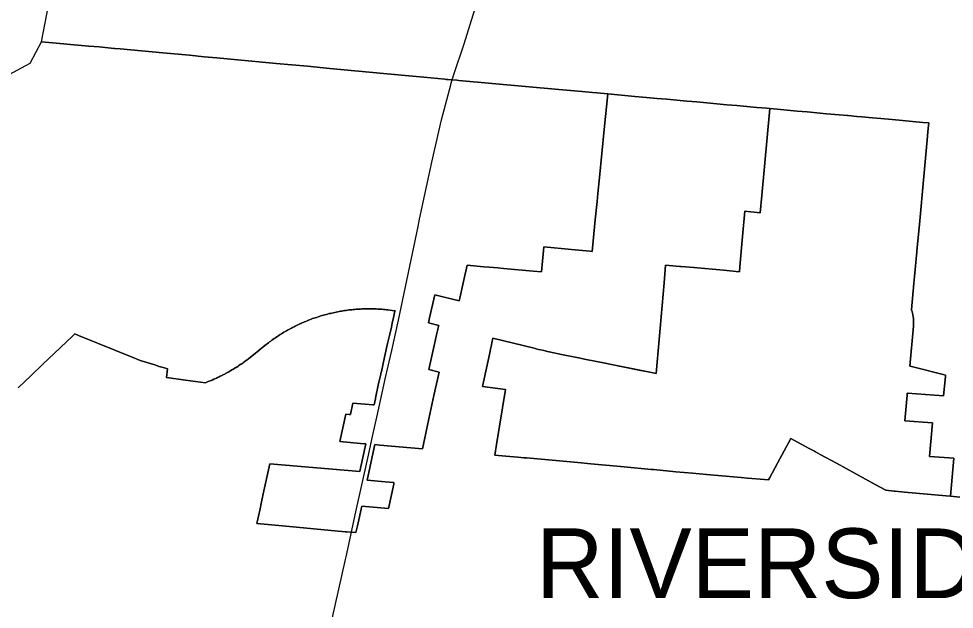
# Model space of a CAD drawing. Extents: x 0 to 34, y 0 to 22.
# Drawn here: x 5.4737 to 5.5815, y 15.4958 to 15.5639 of the extents above; entities that cross this region are included whole.
import ezdxf

# ---------------------------------------------------------------- set-up
doc = ezdxf.new("R2010")
doc.units = 0
for name, color, linetype in [('GM_X_Corporation', 7, 'Continuous'), ('GM_X_Corporation_Text', 7, 'Continuous'), ('GM_X_State_Route', 7, 'Continuous')]:
    doc.layers.add(name, color=color, linetype=linetype)

msp = doc.modelspace()

# ---------------------------------------------------------------- linework, layer by layer
at = {"layer": 'GM_X_Corporation'}
for points in [[(5.58209, 15.50876), (5.58101, 15.50886), (5.58141, 15.51326), (5.5786, 15.51346), (5.57896, 15.51734), (5.57575, 15.51757), (5.57602, 15.5205), (5.57604, 15.52074), (5.57606, 15.52074), (5.58021, 15.52043), (5.58043, 15.52265), (5.58044, 15.52283), (5.58019, 15.5229), (5.57655, 15.52381), (5.57633, 15.52387), (5.57676, 15.52848), (5.57676, 15.52856), (5.57677, 15.52864), (5.57677, 15.52871), (5.57677, 15.52879), (5.57678, 15.52887), (5.57678, 15.52894), (5.57677, 15.52902), (5.57677, 15.5291), (5.57677, 15.52917), (5.57676, 15.52925), (5.57675, 15.52933), (5.57675, 15.52941), (5.57674, 15.52946), (5.57674, 15.52948), (5.57673, 15.52956), (5.57671, 15.52963), (5.5767, 15.52971), (5.57669, 15.52979), (5.57667, 15.52986), (5.57665, 15.52994), (5.57663, 15.53001), (5.57661, 15.53008), (5.57659, 15.53016), (5.57657, 15.53023), (5.57653, 15.53035), (5.57653, 15.53035), (5.57673, 15.53253), (5.57677, 15.53293), (5.57681, 15.53341), (5.57688, 15.53418), (5.57715, 15.53705), (5.57715, 15.53709), (5.57748, 15.5406), (5.57791, 15.54529), (5.5783, 15.54951), (5.57846, 15.55126), (5.57852, 15.55189), (5.57782, 15.55195), (5.57665, 15.55205), (5.57548, 15.55216), (5.57432, 15.55227), (5.57298, 15.55239), (5.57202, 15.55247), (5.57082, 15.55258), (5.57023, 15.55263), (5.56922, 15.55273), (5.56914, 15.55273), (5.56819, 15.55282), (5.56673, 15.55295), (5.56561, 15.55305), (5.5645, 15.55315), (5.56335, 15.55326), (5.56219, 15.55336), (5.56104, 15.55347), (5.56022, 15.55354), (5.55988, 15.55357), (5.55873, 15.55367), (5.55758, 15.55378), (5.55642, 15.55388), (5.55527, 15.55399), (5.55411, 15.55409), (5.55296, 15.5542), (5.55181, 15.5543), (5.55065, 15.5544), (5.5495, 15.55451), (5.54834, 15.55461), (5.54719, 15.55472), (5.54602, 15.55482), (5.54467, 15.55494), (5.54351, 15.55505), (5.54271, 15.55512), (5.54154, 15.55523), (5.54028, 15.55534), (5.53978, 15.55539), (5.53858, 15.5555), (5.53589, 15.55574), (5.52438, 15.55678), (5.52417, 15.5568), (5.52364, 15.55685), (5.52361, 15.55685), (5.5231, 15.5569), (5.52291, 15.55691), (5.52278, 15.55693), (5.52036, 15.55715), (5.51863, 15.55731), (5.51405, 15.55774), (5.50953, 15.55817), (5.50694, 15.55841), (5.50334, 15.55875), (5.50136, 15.55893), (5.50054, 15.55901), (5.50054, 15.55901), (5.49888, 15.55916), (5.49651, 15.55938), (5.49505, 15.55952), (5.49337, 15.55968), (5.49029, 15.55996), (5.48661, 15.5603), (5.48538, 15.56041), (5.48474, 15.56047), (5.48468, 15.56048), (5.48295, 15.56064), (5.48174, 15.56075), (5.4763, 15.56125), (5.47806, 15.57044)], [(5.47209, 15.55721), (5.47501, 15.55879), (5.4763, 15.56125), (5.48174, 15.56075), (5.48295, 15.56064), (5.48468, 15.56048), (5.48474, 15.56047), (5.48538, 15.56042), (5.48661, 15.5603), (5.49029, 15.55996), (5.49337, 15.55968), (5.49505, 15.55952), (5.49651, 15.55938), (5.49888, 15.55916), (5.50053, 15.55901), (5.50136, 15.55893), (5.50334, 15.55875), (5.50694, 15.55841), (5.50953, 15.55817), (5.51405, 15.55774), (5.51863, 15.55731), (5.52035, 15.55715), (5.52278, 15.55693), (5.52291, 15.55691), (5.5231, 15.5569), (5.52361, 15.55685), (5.52364, 15.55685), (5.52417, 15.5568), (5.52438, 15.55678), (5.53589, 15.55574), (5.53858, 15.5555), (5.53978, 15.55539), (5.54028, 15.55534), (5.54154, 15.55523), (5.54113, 15.55111), (5.54058, 15.54558), (5.5404, 15.54375), (5.54031, 15.54285), (5.5401, 15.54073), (5.53974, 15.53708), (5.53949, 15.53711), (5.53735, 15.5373), (5.53416, 15.53759), (5.5339, 15.53474), (5.53295, 15.53482), (5.52954, 15.53512), (5.52888, 15.53518), (5.52789, 15.53526), (5.52728, 15.53531), (5.52534, 15.53548), (5.52493, 15.53362), (5.52451, 15.5317), (5.52444, 15.53139), (5.52161, 15.53206), (5.52102, 15.52942), (5.52089, 15.52885), (5.52206, 15.52856), (5.52203, 15.52844), (5.52196, 15.52811), (5.52195, 15.52809), (5.52185, 15.52762), (5.52182, 15.52748), (5.52169, 15.52694), (5.52091, 15.52346), (5.52091, 15.52346), (5.52091, 15.52346), (5.52091, 15.52346), (5.52211, 15.52316), (5.52152, 15.52046), (5.52094, 15.5178), (5.52089, 15.51758), (5.52066, 15.5165), (5.52058, 15.51615), (5.52019, 15.51434), (5.51529, 15.51477), (5.51472, 15.51482), (5.51384, 15.51071), (5.51591, 15.51053), (5.51691, 15.51044), (5.51688, 15.51026), (5.51627, 15.50746), (5.5132, 15.50773), (5.5127, 15.50545), (5.51253, 15.50467), (5.51202, 15.50472), (5.512, 15.50472), (5.51146, 15.50477), (5.51129, 15.50478), (5.50406, 15.50546), (5.50112, 15.50574), (5.50148, 15.50741), (5.50162, 15.50801), (5.50186, 15.50914), (5.50224, 15.51088), (5.50262, 15.51261), (5.51297, 15.5117), (5.51306, 15.51211), (5.51366, 15.51491), (5.51356, 15.51492), (5.51305, 15.51496), (5.51068, 15.51517), (5.51136, 15.51832), (5.51174, 15.51828), (5.5119, 15.51827), (5.51219, 15.5196), (5.51452, 15.5194), (5.51462, 15.51939), (5.51477, 15.5201), (5.51479, 15.52018), (5.5151, 15.52165), (5.51518, 15.52202), (5.51539, 15.52293), (5.51541, 15.52302), (5.51546, 15.52324), (5.51583, 15.52489), (5.51618, 15.52646), (5.51643, 15.52756), (5.51661, 15.52834), (5.51671, 15.52882), (5.51689, 15.5296), (5.51699, 15.53004), (5.51703, 15.53023), (5.5167, 15.53028), (5.51621, 15.53034), (5.51619, 15.53034), (5.51604, 15.53036), (5.51586, 15.53038), (5.51571, 15.53039), (5.51553, 15.53041), (5.51538, 15.53042), (5.5152, 15.53043), (5.51505, 15.53044), (5.51487, 15.53045), (5.51472, 15.53045), (5.51454, 15.53046), (5.51438, 15.53046), (5.5142, 15.53046), (5.51413, 15.53047), (5.51396, 15.53047), (5.51387, 15.53046), (5.51372, 15.53046), (5.51354, 15.53046), (5.51339, 15.53045), (5.51321, 15.53045), (5.51305, 15.53044), (5.51287, 15.53043), (5.51272, 15.53042), (5.51254, 15.53041), (5.51239, 15.53039), (5.51221, 15.53038), (5.51206, 15.53036), (5.51188, 15.53034), (5.51173, 15.53033), (5.51155, 15.5303), (5.5114, 15.53028), (5.51122, 15.53026), (5.51107, 15.53023), (5.51089, 15.53021), (5.51074, 15.53018), (5.51044, 15.53012), (5.51024, 15.53009), (5.51009, 15.53005), (5.50991, 15.53002), (5.50977, 15.52998), (5.50959, 15.52994), (5.50944, 15.52991), (5.50927, 15.52986), (5.50912, 15.52982), (5.50895, 15.52978), (5.5088, 15.52973), (5.50863, 15.52968), (5.50848, 15.52964), (5.50831, 15.52959), (5.50816, 15.52954), (5.50799, 15.52948), (5.50785, 15.52944), (5.50768, 15.52938), (5.50754, 15.52933), (5.50737, 15.52926), (5.50719, 15.5292), (5.50705, 15.52915), (5.50691, 15.52909), (5.50675, 15.52902), (5.50661, 15.52896), (5.50644, 15.52889), (5.5063, 15.52883), (5.50622, 15.52879), (5.50614, 15.52876), (5.506, 15.52869), (5.50584, 15.52861), (5.5057, 15.52855), (5.50554, 15.52847), (5.5054, 15.5284), (5.50524, 15.52832), (5.50511, 15.52825), (5.50495, 15.52816), (5.50481, 15.52809), (5.50466, 15.528), (5.50452, 15.52793), (5.50437, 15.52784), (5.50424, 15.52776), (5.50408, 15.52766), (5.50395, 15.52758), (5.5038, 15.52749), (5.50367, 15.52741), (5.50352, 15.52731), (5.5034, 15.52722), (5.50325, 15.52712), (5.50312, 15.52704), (5.50297, 15.52693), (5.50285, 15.52684), (5.50271, 15.52674), (5.50258, 15.52665), (5.50244, 15.52654), (5.50204, 15.52623), (5.50074, 15.52517), (5.50059, 15.52505), (5.50014, 15.5247), (5.50005, 15.52463), (5.49987, 15.52449), (5.49977, 15.52443), (5.49958, 15.52429), (5.49949, 15.52422), (5.4993, 15.52409), (5.4992, 15.52403), (5.49901, 15.5239), (5.49891, 15.52383), (5.49872, 15.52371), (5.49862, 15.52365), (5.49842, 15.52352), (5.49832, 15.52347), (5.49812, 15.52335), (5.49802, 15.52329), (5.49782, 15.52317), (5.49778, 15.52315), (5.49772, 15.52312), (5.49752, 15.52301), (5.49741, 15.52295), (5.49721, 15.52284), (5.49711, 15.52279), (5.4969, 15.52269), (5.49679, 15.52264), (5.49668, 15.52258), (5.49659, 15.52253), (5.49648, 15.52249), (5.49627, 15.52239), (5.49616, 15.52234), (5.49595, 15.52225), (5.49585, 15.5222), (5.49563, 15.52211), (5.49552, 15.52207), (5.4952, 15.52194), (5.49289, 15.52225), (5.4907, 15.52255), (5.49081, 15.52355), (5.49058, 15.52362), (5.49048, 15.52365), (5.48987, 15.52383), (5.48937, 15.52399), (5.48768, 15.52451), (5.48694, 15.52482), (5.48056, 15.5274), (5.48014, 15.52757), (5.47983, 15.52727), (5.47647, 15.52407), (5.47512, 15.52278), (5.47361, 15.52134)], [(5.47361, 15.52134), (5.47512, 15.52278), (5.47647, 15.52407), (5.47983, 15.52727), (5.48014, 15.52757), (5.48056, 15.5274), (5.48694, 15.52482), (5.48768, 15.52451), (5.48937, 15.52399), (5.48987, 15.52383), (5.49048, 15.52365), (5.49058, 15.52362), (5.49081, 15.52355), (5.4907, 15.52255), (5.49289, 15.52225), (5.4952, 15.52194), (5.49552, 15.52207), (5.49563, 15.52211), (5.49585, 15.5222), (5.49595, 15.52225), (5.49616, 15.52234), (5.49627, 15.52239), (5.49648, 15.52249), (5.49659, 15.52253), (5.49668, 15.52258), (5.49679, 15.52264), (5.4969, 15.52269), (5.49711, 15.52279), (5.49721, 15.52284), (5.49741, 15.52295), (5.49752, 15.52301), (5.49772, 15.52312), (5.49773, 15.52313), (5.49778, 15.52315), (5.49782, 15.52317), (5.49802, 15.52329), (5.49812, 15.52335), (5.49832, 15.52347), (5.49842, 15.52352), (5.49862, 15.52365), (5.49872, 15.52371), (5.49891, 15.52383), (5.49901, 15.5239), (5.4992, 15.52403), (5.4993, 15.52409), (5.49949, 15.52422), (5.49958, 15.52429), (5.49977, 15.52443), (5.49987, 15.52449), (5.50005, 15.52463), (5.50014, 15.5247), (5.50059, 15.52505), (5.50074, 15.52517), (5.50204, 15.52623), (5.50244, 15.52654), (5.50258, 15.52665), (5.50271, 15.52674), (5.50285, 15.52684), (5.50297, 15.52693), (5.50312, 15.52704), (5.50325, 15.52712), (5.5034, 15.52722), (5.50352, 15.52731), (5.50367, 15.52741), (5.5038, 15.52749), (5.50395, 15.52758), (5.50408, 15.52766), (5.50424, 15.52776), (5.50437, 15.52784), (5.50452, 15.52793), (5.50466, 15.528), (5.50481, 15.52809), (5.50495, 15.52816), (5.50511, 15.52825), (5.50524, 15.52832), (5.5054, 15.5284), (5.50554, 15.52847), (5.5057, 15.52855), (5.50584, 15.52861), (5.506, 15.52869), (5.50614, 15.52876), (5.50622, 15.52879), (5.5063, 15.52883), (5.50644, 15.52889), (5.50661, 15.52896), (5.50675, 15.52902), (5.50691, 15.52909), (5.50705, 15.52915), (5.50719, 15.5292), (5.50737, 15.52926), (5.50754, 15.52933), (5.50768, 15.52938), (5.50785, 15.52944), (5.50799, 15.52948), (5.50816, 15.52954), (5.50831, 15.52959), (5.50848, 15.52964), (5.50863, 15.52968), (5.5088, 15.52973), (5.50895, 15.52978), (5.50912, 15.52982), (5.50927, 15.52986), (5.50944, 15.52991), (5.50959, 15.52994), (5.50977, 15.52998), (5.50991, 15.53002), (5.51009, 15.53005), (5.51024, 15.53009), (5.51042, 15.53012), (5.51044, 15.53012), (5.51074, 15.53018), (5.51089, 15.53021), (5.51107, 15.53023), (5.51122, 15.53026), (5.5114, 15.53028), (5.51155, 15.5303), (5.51173, 15.53033), (5.51188, 15.53034), (5.51206, 15.53036), (5.51221, 15.53038), (5.51239, 15.53039), (5.51254, 15.53041), (5.51272, 15.53042), (5.51287, 15.53043), (5.51305, 15.53044), (5.51321, 15.53045), (5.51339, 15.53045), (5.51354, 15.53046), (5.51372, 15.53046), (5.51396, 15.53047), (5.51413, 15.53047), (5.5142, 15.53046), (5.51438, 15.53046), (5.51454, 15.53046), (5.51472, 15.53045), (5.51487, 15.53045), (5.51505, 15.53044), (5.5152, 15.53043), (5.51538, 15.53042), (5.51553, 15.53041), (5.51571, 15.53039), (5.51586, 15.53038), (5.51604, 15.53036), (5.51619, 15.53034), (5.51621, 15.53034), (5.5167, 15.53028), (5.51703, 15.53023), (5.51699, 15.53004), (5.51689, 15.5296), (5.51671, 15.52882), (5.51661, 15.52834), (5.51643, 15.52756), (5.51618, 15.52646), (5.51583, 15.52489), (5.51546, 15.52324), (5.51541, 15.52302), (5.51539, 15.52293), (5.51518, 15.52202), (5.5151, 15.52165), (5.51479, 15.52018), (5.51477, 15.5201), (5.51462, 15.51939), (5.51452, 15.5194), (5.51219, 15.5196), (5.5119, 15.51827), (5.51174, 15.51828), (5.51136, 15.51832), (5.51068, 15.51517), (5.51305, 15.51496), (5.51356, 15.51492), (5.51366, 15.51491), (5.51306, 15.51211), (5.51297, 15.5117), (5.50262, 15.51261), (5.50224, 15.51088), (5.50186, 15.50914), (5.50162, 15.50801), (5.50148, 15.50741), (5.50112, 15.50574), (5.50406, 15.50546), (5.51129, 15.50478), (5.51146, 15.50477), (5.512, 15.50472), (5.51202, 15.50472), (5.51253, 15.50467), (5.5127, 15.50545), (5.5132, 15.50773), (5.51627, 15.50746), (5.51688, 15.51026), (5.51691, 15.51044), (5.51591, 15.51053), (5.51384, 15.51071), (5.51472, 15.51482), (5.51529, 15.51477), (5.52019, 15.51434), (5.52058, 15.51615), (5.52066, 15.5165), (5.52089, 15.51758), (5.52094, 15.5178), (5.52152, 15.52046), (5.52211, 15.52316), (5.52091, 15.52346), (5.52169, 15.52694), (5.52182, 15.52748), (5.52185, 15.52762), (5.52195, 15.52809), (5.52196, 15.52811), (5.52203, 15.52844), (5.52206, 15.52856), (5.52089, 15.52885), (5.52102, 15.52942), (5.52161, 15.53206), (5.52444, 15.53139), (5.52451, 15.5317), (5.52493, 15.53362), (5.52534, 15.53548), (5.52728, 15.53531), (5.52789, 15.53526), (5.52888, 15.53518), (5.52954, 15.53512), (5.53295, 15.53482), (5.5339, 15.53474), (5.53416, 15.53759), (5.53735, 15.5373), (5.53949, 15.53711), (5.53974, 15.53708), (5.5401, 15.54073), (5.54031, 15.54285), (5.5404, 15.54375), (5.54058, 15.54558), (5.54113, 15.55111), (5.54154, 15.55523), (5.54271, 15.55512), (5.54351, 15.55505), (5.54467, 15.55494), (5.54602, 15.55482), (5.54719, 15.55472), (5.54834, 15.55461), (5.5495, 15.55451), (5.55065, 15.5544), (5.55181, 15.5543), (5.55296, 15.5542), (5.55411, 15.55409), (5.55527, 15.55399), (5.55642, 15.55388), (5.55758, 15.55378), (5.55873, 15.55367), (5.55988, 15.55357), (5.56022, 15.55354), (5.55929, 15.54353), (5.55911, 15.54154), (5.55735, 15.5417), (5.55708, 15.5388), (5.55676, 15.53532), (5.55671, 15.53474), (5.55487, 15.5349), (5.55145, 15.53521), (5.54999, 15.53534), (5.54985, 15.53535), (5.5486, 15.53547), (5.5482, 15.5355), (5.54802, 15.53344), (5.5471, 15.523), (5.54619, 15.52319), (5.54179, 15.52408), (5.54123, 15.52419), (5.53904, 15.52464), (5.53817, 15.52481), (5.53622, 15.52521), (5.5348, 15.52549), (5.53474, 15.52551), (5.53459, 15.52554), (5.53416, 15.52565), (5.53382, 15.52573), (5.53358, 15.52579), (5.5333, 15.52586), (5.53308, 15.52592), (5.52831, 15.52709), (5.52819, 15.52654), (5.52809, 15.52607), (5.52808, 15.526), (5.52794, 15.52539), (5.52711, 15.52151), (5.52976, 15.52116), (5.52871, 15.51481), (5.52852, 15.51361), (5.52978, 15.5135), (5.53118, 15.51337), (5.53186, 15.51331), (5.53218, 15.51328), (5.5381, 15.51274), (5.5396, 15.5126), (5.54343, 15.51224), (5.54653, 15.51196), (5.54686, 15.51193), (5.5494, 15.51169), (5.5513, 15.51152), (5.5521, 15.51144), (5.55293, 15.51136), (5.5569, 15.51102), (5.55763, 15.51095), (5.55958, 15.51078), (5.56007, 15.51074), (5.56018, 15.51094), (5.5611, 15.51267), (5.56263, 15.51553), (5.56426, 15.51464), (5.56482, 15.51434), (5.56534, 15.51405), (5.56549, 15.51397), (5.56573, 15.51383), (5.56602, 15.51368), (5.56788, 15.51266), (5.57233, 15.51023), (5.57358, 15.50955), (5.57454, 15.50946), (5.5746, 15.50945), (5.57465, 15.50945), (5.57574, 15.50935), (5.58051, 15.50891), (5.58101, 15.50886), (5.58209, 15.50876)]]:
    msp.add_lwpolyline(points, dxfattribs=at)
msp.add_lwpolyline([(5.52711, 15.52151), (5.52794, 15.52539), (5.52808, 15.526), (5.52809, 15.52607), (5.52819, 15.52654), (5.52831, 15.52709), (5.53308, 15.52592), (5.5333, 15.52586), (5.53358, 15.52579), (5.53382, 15.52573), (5.53416, 15.52565), (5.53459, 15.52554), (5.53474, 15.52551), (5.5348, 15.52549), (5.53622, 15.52521), (5.53817, 15.52481), (5.53904, 15.52464), (5.54123, 15.52419), (5.54179, 15.52408), (5.54517, 15.52339), (5.54619, 15.52319), (5.5471, 15.523), (5.54802, 15.53344), (5.5482, 15.5355), (5.5486, 15.53547), (5.54985, 15.53535), (5.54999, 15.53534), (5.55145, 15.53521), (5.55487, 15.5349), (5.55671, 15.53474), (5.55676, 15.53532), (5.55708, 15.5388), (5.55735, 15.5417), (5.55911, 15.54153), (5.55929, 15.54353), (5.56022, 15.55354), (5.56104, 15.55347), (5.56219, 15.55336), (5.56335, 15.55326), (5.5645, 15.55315), (5.56561, 15.55305), (5.56673, 15.55295), (5.56819, 15.55282), (5.56915, 15.55273), (5.56922, 15.55273), (5.57023, 15.55263), (5.57082, 15.55258), (5.57202, 15.55247), (5.57298, 15.55239), (5.57432, 15.55227), (5.57548, 15.55216), (5.57665, 15.55205), (5.57782, 15.55195), (5.57852, 15.55189), (5.57846, 15.55126), (5.5783, 15.54951), (5.57791, 15.54529), (5.57748, 15.5406), (5.57715, 15.53709), (5.57715, 15.53705), (5.57688, 15.53418), (5.57681, 15.53341), (5.57677, 15.53293), (5.57673, 15.53253), (5.57653, 15.53035), (5.57653, 15.53035), (5.57657, 15.53023), (5.57659, 15.53016), (5.57661, 15.53008), (5.57663, 15.53001), (5.57665, 15.52994), (5.57667, 15.52986), (5.57669, 15.52979), (5.5767, 15.52971), (5.57671, 15.52963), (5.57673, 15.52956), (5.57674, 15.52948), (5.57674, 15.52946), (5.57675, 15.52941), (5.57675, 15.52933), (5.57676, 15.52925), (5.57677, 15.52917), (5.57677, 15.5291), (5.57677, 15.52902), (5.57678, 15.52894), (5.57678, 15.52887), (5.57677, 15.52879), (5.57677, 15.52871), (5.57677, 15.52864), (5.57676, 15.52856), (5.57676, 15.52848), (5.57633, 15.52387), (5.57633, 15.52386), (5.57655, 15.52381), (5.58019, 15.5229), (5.58044, 15.52283), (5.58043, 15.52265), (5.58021, 15.52043), (5.57606, 15.52074), (5.57604, 15.52074), (5.57602, 15.5205), (5.57575, 15.51757), (5.57896, 15.51734), (5.5786, 15.51346), (5.5786, 15.51346), (5.5786, 15.51345), (5.5786, 15.51346), (5.58141, 15.51326), (5.58101, 15.50886), (5.58051, 15.50891), (5.57574, 15.50935), (5.57465, 15.50945), (5.5746, 15.50945), (5.57454, 15.50946), (5.57358, 15.50955), (5.57233, 15.51023), (5.56788, 15.51266), (5.56602, 15.51368), (5.56573, 15.51383), (5.56549, 15.51397), (5.56534, 15.51405), (5.56482, 15.51434), (5.56426, 15.51464), (5.56263, 15.51553), (5.5611, 15.51267), (5.56018, 15.51094), (5.56007, 15.51074), (5.55958, 15.51078), (5.55763, 15.51095), (5.5569, 15.51102), (5.55293, 15.51136), (5.5521, 15.51144), (5.5513, 15.51152), (5.5494, 15.51169), (5.54686, 15.51193), (5.54653, 15.51196), (5.54343, 15.51224), (5.5396, 15.5126), (5.5381, 15.51274), (5.53218, 15.51328), (5.53186, 15.51331), (5.53118, 15.51337), (5.52978, 15.5135), (5.52852, 15.51361), (5.52871, 15.51481), (5.52976, 15.52116)], close=True, dxfattribs=at)
at = {"layer": 'GM_X_State_Route'}
for points in [[(5.52348, 15.55637), (5.52379, 15.55746), (5.525, 15.561), (5.52602, 15.56436), (5.5275, 15.56897), (5.52911, 15.5734), (5.53285, 15.5846), (5.53374, 15.58749), (5.53518, 15.59183), (5.53692, 15.59741)], [(5.51986, 15.54078), (5.52128, 15.54735), (5.52239, 15.55226), (5.52346, 15.55629), (5.52348, 15.55637)], [(5.51743, 15.52915), (5.51968, 15.53995), (5.51986, 15.54078)], [(5.51445, 15.51576), (5.51515, 15.519), (5.51593, 15.52256), (5.51665, 15.52567), (5.51743, 15.52915)], [(5.51133, 15.50156), (5.5114, 15.5019), (5.51252, 15.50707), (5.51391, 15.51326), (5.51445, 15.51576)], [(5.50911, 15.49145), (5.50931, 15.49238), (5.50981, 15.49475), (5.51133, 15.50156)]]:
    msp.add_lwpolyline(points, dxfattribs=at)

# ---------------------------------------------------------------- texts
at = {"layer": 'GM_X_Corporation_Text'}
msp.add_text('RIVERSIDE', height=0.008037, rotation=0, dxfattribs=at).set_placement((5.53329, 15.49712))

doc.saveas('drawing.dxf')
